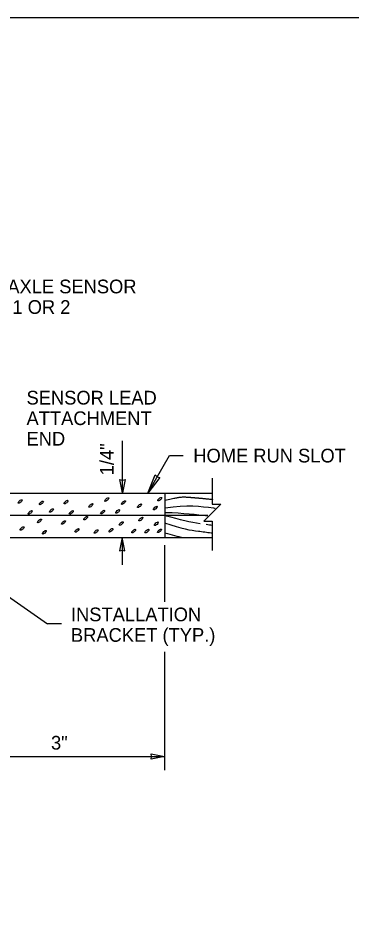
# Model space of a CAD drawing. Extents: x 99862 to 103151, y 100000 to 108076.
# Drawn here: x 102183 to 102573, y 104032 to 105076 of the extents above; entities that cross this region are included whole.
import ezdxf

# ---------------------------------------------------------------- set-up
doc = ezdxf.new("R2010")
doc.units = 0
for name, color, linetype in [('Level 1', 7, 'Continuous'), ('Level 15', 7, 'Continuous'), ('Level 16', 7, 'Continuous'), ('Level 18', 7, 'Continuous'), ('Level 20', 7, 'Continuous'), ('Level 32', 7, 'Continuous'), ('Level 6', 7, 'Continuous')]:
    doc.layers.add(name, color=color, linetype=linetype)

msp = doc.modelspace()

# ---------------------------------------------------------------- linework, layer by layer
at = {"layer": 'Level 1'}
msp.add_lwpolyline([(99862, 102999.5), (103151, 102999.5), (103151, 105075.5), (99862, 105075.5)], close=True, dxfattribs=at)
at = {"layer": 'Level 15'}
for p, q in [((102305.6, 104520.6), (102305.6, 104581.3)), ((102335.2, 104520.4), (102360.4, 104564.1)), ((102360.4, 104564.1), (102376.4, 104564.1)), ((102355, 104520.4), (102355, 104501.6)), ((102355, 104501.6), (102355, 104468.4)), ((102305.1, 104468.5), (102305.1, 104436.7)), ((102354.7, 104459.5), (102354.7, 104393.4)), ((102092.6, 104455.3), (102217.9, 104367.6)), ((102234.2, 104367.6), (102217.9, 104367.6)), ((102354.7, 104334.7), (102354.7, 104196.7)), ((102102.8, 104212.7), (102354.7, 104212.7))]:
    msp.add_line(p, q, dxfattribs=at)
for points in [[(102335.2, 104520.4), (102344, 104541.7), (102346.1, 104539.3), (102349.2, 104538.7)], [(102305.6, 104520.6), (102302.5, 104536.4), (102305.6, 104535.6), (102308.7, 104536.4)], [(102305.1, 104468.5), (102302, 104452.7), (102305.1, 104453.5), (102308.2, 104452.7)], [(102354.7, 104212.7), (102339, 104209.6), (102339.7, 104212.7), (102339, 104215.8)]]:
    msp.add_lwpolyline(points, close=True, dxfattribs=at)
msp.add_lwpolyline([(102410.5, 104537.8), (102410.5, 104507.4), (102420.4, 104507.4), (102400.6, 104487.6), (102410.5, 104487.6), (102410.5, 104453.1)], dxfattribs=at)
at = {"layer": 'Level 16'}
for points, degree in [([(102355.3, 104512.1), (102372.9, 104516.2), (102379.6, 104515.8), (102386.6, 104515.3), (102393.9, 104514.7), (102402.1, 104513.9), (102411.3, 104513)], 4), ([(102355.5, 104503.3), (102381.5, 104507), (102396.8, 104505), (102412.1, 104503)], 3), ([(102412.1, 104503), (102412.8, 104502.9), (102413.4, 104502.8), (102414, 104502.7)], 3), ([(102355.2, 104494.2), (102372.9, 104489.2), (102385.5, 104486.7), (102396.5, 104484.9)], 3), ([(102355.7, 104497.8), (102377.4, 104497), (102391.7, 104495.5), (102404.9, 104493.8)], 3), ([(102354.9, 104485.6), (102375.2, 104478.3), (102385.1, 104477.1), (102394.3, 104476)], 3), ([(102403.4, 104483.9), (102405.9, 104483.5), (102408.4, 104483.2), (102410.8, 104482.9)], 3), ([(102355.2, 104473.8), (102363.2, 104471.6), (102370.2, 104469.8), (102376.5, 104468.4)], 3), ([(102394.3, 104476), (102396.8, 104475.6), (102399.3, 104475.3), (102401.8, 104474.9)], 3), ([(102401.8, 104474.9), (102404.3, 104474.6), (102406.7, 104474.2), (102409.2, 104473.9)], 3), ([(102409.1, 104473.9), (102409.6, 104473.8), (102410, 104473.8), (102410.5, 104473.7)], 3)]:
    msp.add_open_spline(points, degree=degree, dxfattribs=at)
at = {"layer": 'Level 18'}
for p, q in [((102107.8, 104520.4), (102410.5, 104520.4)), ((102107.8, 104468.4), (102410.5, 104468.4))]:
    msp.add_line(p, q, dxfattribs=at)
at = {"layer": 'Level 32'}
for centre in [(102186, 104510.5), (102210.9, 104508.8), (102239.7, 104509.9), (102287.3, 104512.8), (102306.8, 104509.2), (102349.2, 104513.2), (102197.7, 104497.8), (102222.6, 104500), (102245.8, 104497.8), (102268.7, 104505.9), (102282.4, 104498.2), (102300.1, 104499), (102325.5, 104505.6), (102344, 104502.9), (102208.7, 104487.8), (102262.6, 104491), (102327.1, 104490), (102188.3, 104479), (102236.7, 104486), (102252.4, 104476.8), (102292.3, 104476.9), (102304.2, 104484.8), (102345.3, 104484.6), (102214.3, 104474.5), (102274.8, 104475.5), (102318.7, 104476), (102334.2, 104475.9), (102348.9, 104476.2)]:
    msp.add_ellipse(centre, major_axis=(2.21, 1.94), ratio=0.362832, dxfattribs=at)
at = {"layer": 'Level 6'}
for p, q in [((102113.1, 104494.4), (102354.8, 104494.4)), ((102354.8, 104494.4), (102405.5, 104494.4))]:
    msp.add_line(p, q, dxfattribs=at)

# ---------------------------------------------------------------- texts
at = {"layer": 'Level 20'}
for s, rotation, p in [('PIEZO AXLE SENSOR', 360, (102100.9, 104753.7)), ('CLASS 1 OR 2', 360, (102100.9, 104729.7)), ('SENSOR LEAD', 360, (102193.5, 104623.8)), ('ATTACHMENT', 360, (102193.5, 104599.8)), ('END', 360, (102193.5, 104575.8)), (' 1/4"', 90, (102295.3, 104535.2)), ('3" ', 360, (102222.1, 104220.7))]:
    msp.add_text(s, height=16, rotation=rotation, dxfattribs=at).set_placement(p)
for s, p in [('HOME RUN SLOT', (102388.4, 104556.1)), ('INSTALLATION ', (102245.4, 104370.6)), ('BRACKET (TYP.) ', (102245.4, 104346.6))]:
    msp.add_text(s, height=16, dxfattribs=at).set_placement(p)

doc.saveas('drawing.dxf')
